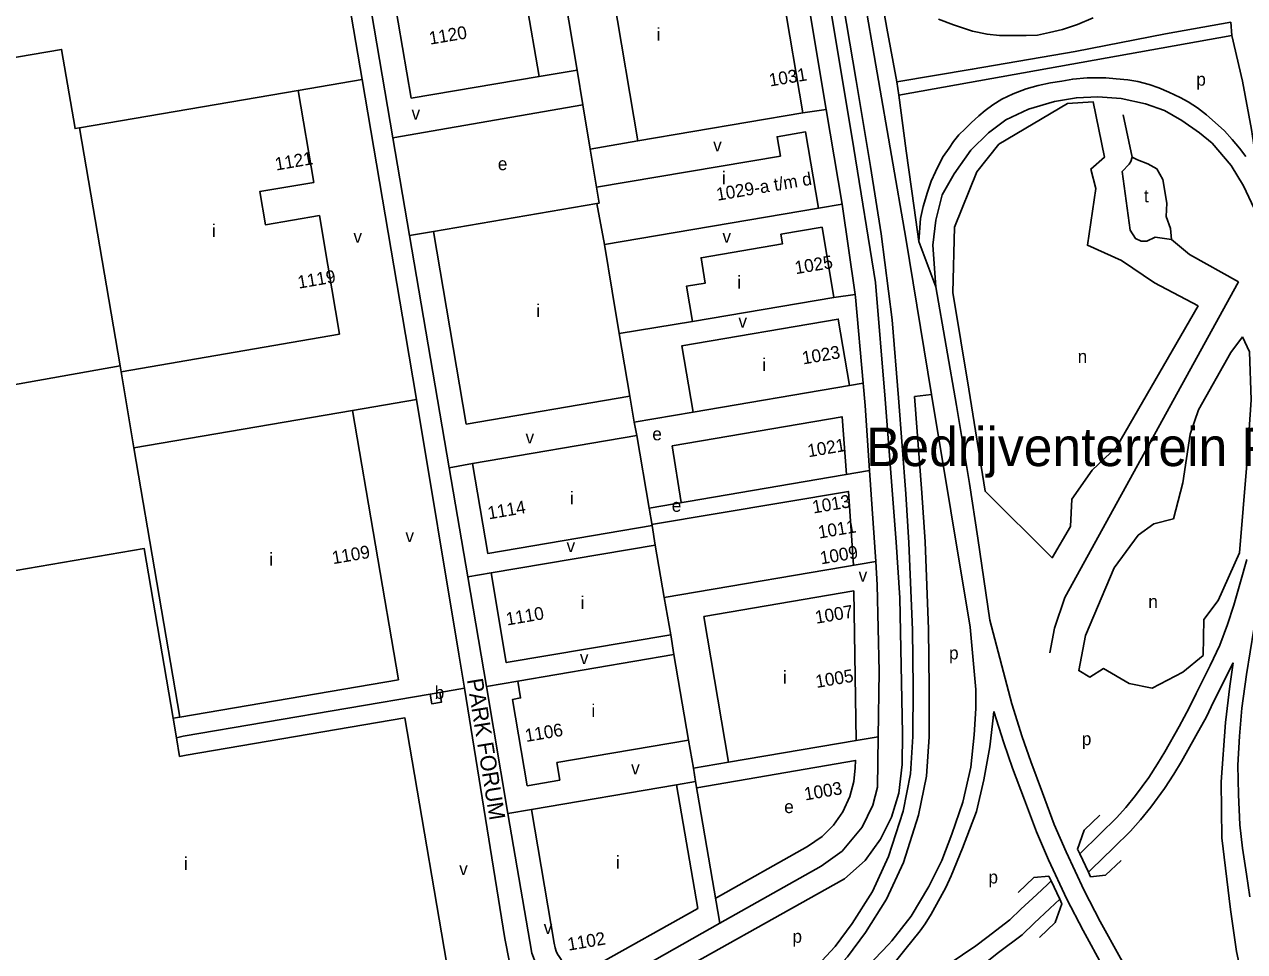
# Model space of a CAD drawing. Extents: x 154320 to 156262, y 382651 to 384180.
# Drawn here: x 154804.6 to 155184.2, y 383220 to 383508.4 of the extents above; entities that cross this region are included whole.
import ezdxf

# ---------------------------------------------------------------- set-up
doc = ezdxf.new("R2010")
doc.units = 0
for name, color, linetype in [('BLT_Basislijn', 7, 'Continuous'), ('BLT_Bebouwing', 7, 'Continuous'), ('BLT_Centroide', 7, 'Continuous'), ('BLT_Huisnummer', 7, 'Continuous'), ('BLT_Huisnummer_reeks', 7, 'Continuous'), ('BLT_Huisnummer_zonder_bebouwing', 7, 'Continuous'), ('BLT_Onderverdeling_panden', 7, 'Continuous'), ('BLT_Plantopo', 7, 'Continuous'), ('BLT_Sport_parknaam', 7, 'Continuous'), ('BLT_Straatnaam', 7, 'Continuous'), ('BLT_Vlakafsluiter', 7, 'Continuous')]:
    doc.layers.add(name, color=color, linetype=linetype)

msp = doc.modelspace()

# ---------------------------------------------------------------- linework, layer by layer
at = {"layer": 'BLT_Basislijn'}
for p, q in [((154904.98, 383556.75), (154919.23, 383473.09)), ((154976.53, 383494.14), (154969.79, 383534.71)), ((155179.9, 383509.09), (155180.25, 383504.95)), ((154889.72, 383487.81), (154909.63, 383491.26)), ((154964.69, 383492.17), (154976.53, 383494.14)), ((154978.32, 383483.35), (154976.53, 383494.14)), ((155075.98, 383490.54), (155076.69, 383486.41)), ((154919.23, 383473.09), (154978.32, 383483.35)), ((154980.61, 383469.6), (154978.32, 383483.35)), ((155149.29, 383467.05), (155146.42, 383480.21)), ((154919.23, 383473.09), (154924.4, 383442.77)), ((155051.66, 383451.27), (155058.97, 383452.51)), ((154931.81, 383444.01), (154924.4, 383442.77)), ((154924.4, 383442.77), (154936.71, 383370.48)), ((155086.84, 383393.25), (155078.78, 383441.91)), ((155056.45, 383423.4), (155063.02, 383424.42)), ((155012.45, 383416.01), (154989.66, 383412.19)), ((154834.64, 383400.33), (154838.62, 383376.66)), ((155061.31, 383396.08), (155065.58, 383396.8)), ((154994.33, 383384.69), (154992.97, 383392.72)), ((155081.53, 383392.66), (155086.84, 383393.25)), ((155098.84, 383320.87), (155086.84, 383393.25)), ((154906.67, 383388.27), (154926.55, 383391.66)), ((155012.64, 383387.8), (154994.33, 383384.69)), ((154994.33, 383384.69), (154995.07, 383380.54)), ((154943.97, 383371.79), (154936.71, 383370.48)), ((154936.71, 383370.48), (154942.49, 383336.54)), ((155067.56, 383369.59), (154998.94, 383357.92)), ((155069.45, 383341.32), (155067.56, 383369.59)), ((155000.87, 383346.44), (154999.86, 383352.54)), ((155100.63, 383301.5), (155098.84, 383320.87)), ((154933.81, 383300.57), (154941.46, 383301.92)), ((154958.07, 383304.07), (154948.31, 383302.4)), ((154853.92, 383287), (154930.79, 383300.07)), ((154850.83, 383292.59), (154852.87, 383292.89)), ((154851.86, 383286.5), (154853.92, 383287)), ((155011.21, 383285.75), (155012.71, 383277.03)), ((155063.33, 383285.63), (155070.22, 383286.8)), ((155023.64, 383278.89), (155012.71, 383277.03)), ((155012.71, 383277.03), (155013.42, 383272.88)), ((155013.42, 383272.88), (155007.49, 383271.87)), ((155013.42, 383272.88), (155020.99, 383228.79)), ((154962.3, 383264.15), (154955.03, 383262.9))]:
    msp.add_line(p, q, dxfattribs=at)
for points in [[(155023.31, 383706.47), (155038.2, 383616.87), (155062.68, 383469.79), (155069.36, 383428.11)], [(155036.13, 383685.14), (155036.76, 383683.03), (155038.71, 383673.47), (155078.78, 383441.91)], [(155048.57, 383212.61), (155056.82, 383221.58), (155062.17, 383228.69), (155068.4, 383238.67), (155073.45, 383249.51), (155077.96, 383263.67), (155080.28, 383275.23), (155081.04, 383286.89), (155081.1, 383302.07), (155080.89, 383320.08), (155079.8, 383347.13), (155078.77, 383362.31), (155076.55, 383392.27), (155074.59, 383416.48), (155071.13, 383443.2), (155067.82, 383464.17), (155063.32, 383490.92), (155056.28, 383532.64), (155051.11, 383563.15)], [(155054.06, 383481.93), (155045.91, 383530.45), (155043.13, 383547.03)], [(155075.98, 383490.54), (155072.91, 383507.2), (155071.26, 383516.65), (155069.72, 383523.86), (155068.19, 383529.88)], [(154909.63, 383491.26), (154903.62, 383526.48)], [(155088.97, 383510.03), (155093.69, 383508.26), (155099.6, 383506.25), (155104.08, 383505.31), (155107.98, 383504.95), (155112.47, 383504.95), (155116.25, 383504.95), (155119.79, 383505.07), (155123.57, 383505.9), (155127.58, 383506.84), (155132.19, 383508.38), (155137.15, 383510.39)], [(155179.9, 383509.09), (155159.58, 383505.43), (155131.48, 383499.99), (155099.48, 383494.44), (155075.98, 383490.54)], [(155076.69, 383486.41), (155180.25, 383504.95)], [(155180.25, 383504.95), (155183.56, 383490.78), (155186.39, 383475.66), (155187.57, 383467.39), (155187.93, 383460.65)], [(154926.55, 383391.66), (154923.17, 383411.93), (154909.63, 383491.26)], [(155184.62, 383467.27), (155182.61, 383469.87), (155180.37, 383472.59), (155178.01, 383475.3), (155175.05, 383477.9), (155172.34, 383480.26), (155169.62, 383482.39), (155166.67, 383484.28), (155164.19, 383485.7), (155160.65, 383487.35), (155157.58, 383488.65), (155154.51, 383489.71), (155150.97, 383490.66), (155147.89, 383491.13), (155144.23, 383491.49), (155141.05, 383491.72), (155138.09, 383491.72), (155135.26, 383491.72), (155130.77, 383491.37), (155127.35, 383490.78), (155123.81, 383490.19), (155120.03, 383489.36), (155116.25, 383488.3), (155112.23, 383486.76), (155108.69, 383485.11)], [(155082.83, 383440.81), (155081.41, 383451.32), (155078.93, 383469.04), (155076.69, 383486.41)], [(155108.69, 383485.11), (155105.86, 383483.34), (155103.49, 383481.56), (155101.49, 383479.91), (155099.13, 383477.78), (155097.24, 383475.89), (155095.35, 383474), (155093.69, 383471.99), (155092.28, 383469.87), (155090.39, 383467.27), (155089.44, 383465.38), (155088.03, 383462.54), (155086.73, 383459.59), (155085.55, 383456.16), (155084.25, 383451.79), (155083.42, 383448.01), (155082.83, 383440.81)], [(155088.2, 383426.75), (155087.26, 383439.74), (155088.2, 383447.54), (155090.09, 383455.34), (155093.87, 383461.95), (155099.07, 383469.28), (155104.5, 383474.71), (155109.93, 383478.73), (155117.02, 383482.03), (155125.05, 383484.4), (155131.89, 383485.58), (155138.51, 383485.81)], [(155138.51, 383485.81), (155145.83, 383485.34), (155153.39, 383483.69), (155159.29, 383481.56), (155164.72, 383478.49), (155170.15, 383474.71), (155174.17, 383471.4), (155180.07, 383464.55), (155183.85, 383458.17), (155187.16, 383451.08), (155188.81, 383444.47)], [(155054.06, 383481.93), (155046.76, 383480.84)], [(155058.97, 383452.51), (155054.06, 383481.93)], [(154995.44, 383472.21), (154980.61, 383469.6)], [(154980.61, 383469.6), (154982.6, 383457.71)], [(155161.5, 383441.46), (155156.39, 383442.16), (155153.76, 383440.93), (155152.02, 383440.93), (155150.24, 383441.74), (155148.67, 383444.37), (155146.08, 383462.61), (155148.26, 383464.88), (155148.81, 383465.75), (155149.29, 383467.05)], [(155149.29, 383467.05), (155150.92, 383466.23), (155154.14, 383464.99), (155156.9, 383463.46), (155158.81, 383460.19), (155159.98, 383452.82), (155159.86, 383448.62), (155161.21, 383444.92), (155161.5, 383441.46)], [(155063.02, 383424.42), (155058.97, 383452.51)], [(155161.5, 383441.46), (155167.08, 383436.78), (155182.28, 383428.33)], [(155193.98, 383439.68), (155194.8, 383434.25), (155195.75, 383423.85), (155196.46, 383412.51), (155196.93, 383398.69), (155196.81, 383385.34), (155196.69, 383371.28), (155195.75, 383362.66), (155194.09, 383353.44), (155191.97, 383342.81), (155187.13, 383320.25), (155184.77, 383306.19), (155183.35, 383295.68), (155182.64, 383286.93), (155182.17, 383277.95), (155182.29, 383268.86), (155182.76, 383259.41), (155183.59, 383252.08), (155184.77, 383244.05), (155185.83, 383236.96)], [(154996.32, 383207.14), (155059.77, 383242.54), (155066.19, 383248.26), (155070.95, 383254.88), (155074.34, 383261.77), (155076.64, 383269.21), (155077.68, 383278.13), (155077.79, 383287.81), (155076.91, 383330.03), (155075.76, 383347.31), (155072.43, 383391.78), (155069.36, 383428.11)], [(155101.19, 383348.54), (155098.59, 383365.55), (155094.58, 383389.89), (155088.2, 383426.75)], [(155182.28, 383428.33), (155128.33, 383330.11), (155125.03, 383320.55), (155123.64, 383312.91)], [(154989.66, 383412.19), (154987.4, 383425.43)], [(155065.58, 383396.8), (155063.14, 383423.56), (155063.02, 383424.42)], [(155067.56, 383369.59), (155066.21, 383389.86), (155065.58, 383396.8)], [(155054.29, 383211.44), (155060.67, 383218.37), (155066.3, 383225.86), (155072.8, 383236.28), (155078.11, 383247.69), (155082.81, 383262.42), (155085.25, 383274.57), (155086.04, 383286.72), (155086.1, 383302.09), (155085.89, 383320.21), (155084.8, 383347.4), (155083.76, 383362.67), (155081.53, 383392.66)], [(154941.46, 383301.92), (154939.76, 383312.44), (154926.55, 383391.66)], [(155104.98, 383323.07), (155101.19, 383348.54)], [(155003.67, 383330.13), (155069.45, 383341.32)], [(155070.22, 383286.8), (155070.53, 383307.05), (155069.93, 383334.07), (155069.45, 383341.32)], [(155132.91, 383250.38), (155139.25, 383256.56), (155144.36, 383261.52), (155147.25, 383264.79), (155150.32, 383268.55), (155154.4, 383274.12), (155157.15, 383278.41), (155159.45, 383282.09), (155163.82, 383290.01), (155167.01, 383295.76), (155169.14, 383300.27), (155173.52, 383308.98), (155176.51, 383315.32), (155178.87, 383321.66), (155180.87, 383327.77), (155182.98, 383334.97), (155184.9, 383341.94)], [(154949.76, 383337.78), (154942.49, 383336.54)], [(154942.49, 383336.54), (154948.31, 383302.4)], [(155104.98, 383323.07), (155111.77, 383297), (155115.05, 383286.74), (155117.68, 383279.04), (155121.32, 383269.31), (155125, 383259.47), (155128.71, 383250.96), (155134.33, 383238.91), (155139.25, 383229.29), (155145.56, 383217.96), (155151.05, 383208.9), (155157.44, 383199.46), (155163.16, 383190.49), (155170.12, 383180.15), (155177.37, 383170.22), (155184.2, 383161.54)], [(155006.66, 383312.34), (155005.67, 383318.49)], [(155135.62, 383244.68), (155136.5, 383245.5), (155143.44, 383252.26), (155148.7, 383257.37), (155151.82, 383260.91), (155155.07, 383264.87), (155159.35, 383270.72), (155162.22, 383275.2), (155164.63, 383279.04), (155169.07, 383287.1), (155172.35, 383293.02), (155174.53, 383297.64), (155180.64, 383309.78)], [(155180.64, 383309.78), (155179.65, 383302.54), (155178.31, 383291.22), (155176.97, 383272.74), (155177.19, 383255.3), (155179.8, 383233.1)], [(154967.74, 383198.42), (154968.4, 383199.95), (154968.1, 383201.56), (154966.98, 383202.8), (154964.01, 383204.72), (154960.79, 383207.32), (154958.01, 383211.21), (154955.47, 383216.66), (154954.05, 383224.08), (154941.46, 383301.92)], [(154948.31, 383302.4), (154955.03, 383262.9)], [(155100.63, 383301.5), (155100.55, 383295.54), (155100.1, 383287.34), (155099.06, 383277.36), (155096.53, 383266.48), (155093.1, 383256.5), (155089.98, 383248.3), (155085.95, 383240.25), (155080.44, 383231.01), (155074.48, 383223.26), (155073.56, 383222.3)], [(155106.23, 383294.63), (155105.76, 383290.76), (155104.94, 383283.65), (155103.05, 383273.41), (155100.81, 383263.57), (155096.49, 383252.1), (155092.88, 383243.53), (155091.29, 383239.85), (155089.51, 383236.63), (155086.75, 383231.55), (155084.8, 383228.64)], [(155106.23, 383294.63), (155109.35, 383284.86), (155112.03, 383277.02), (155115.7, 383267.21), (155119.44, 383257.22), (155123.24, 383248.49), (155128.94, 383236.28), (155133.95, 383226.47), (155140.37, 383214.95), (155146, 383205.66), (155152.43, 383196.17), (155160.82, 383182.98)], [(155020.99, 383228.79), (155052.43, 383246.53), (155058.97, 383251.2), (155065.21, 383258.69), (155068.52, 383265.55), (155069.98, 383271.15), (155070.22, 383286.8)], [(154955.03, 383262.9), (154962.43, 383219.49), (154963.8, 383215.97), (154965.69, 383213.14), (154967.91, 383210.89), (154970.82, 383209), (154975.1, 383207.49), (154980.13, 383207.29), (154984.71, 383208.39)], [(155139.19, 383262.36), (155134.3, 383257.72), (155132.21, 383251.86), (155132.91, 383250.38)], [(155132.91, 383250.38), (155135.62, 383244.68)], [(155135.62, 383244.68), (155136.31, 383243.24), (155140.94, 383243.71), (155145.82, 383248.32)], [(155093.83, 383217.17), (155096.48, 383218.97), (155100.63, 383221.74), (155104.04, 383224.39), (155111.14, 383229.79), (155114.63, 383233.11), (155119.55, 383237.73), (155122.86, 383240.84), (155124.01, 383241.96)], [(155113.74, 383238.36), (155118.65, 383242.96), (155123.29, 383243.47), (155124.01, 383241.96)], [(155124.01, 383241.96), (155126.71, 383236.23)], [(155097.57, 383212.45), (155099.83, 383213.99), (155104.15, 383216.88), (155107.7, 383219.64), (155115.03, 383225.21), (155118.75, 383228.75), (155123.66, 383233.36), (155126.71, 383236.23)], [(155126.71, 383236.23), (155127.37, 383234.82), (155125.27, 383228.96), (155120.38, 383224.34)], [(155179.8, 383233.1), (155181.73, 383219.99), (155184.12, 383208.96), (155186.05, 383200.91), (155187.54, 383194.95), (155190.37, 383187.8), (155192.61, 383182.58), (155195.58, 383176.47), (155199.01, 383170.07), (155202.73, 383163.66), (155206.61, 383158.74), (155211.97, 383152.18), (155217.63, 383146.37), (155223.74, 383141.16), (155229.25, 383137.28), (155236.55, 383132.66), (155242.95, 383129.23), (155248.17, 383127.3), (155255.17, 383125.06), (155263.36, 383121.93), (155269.62, 383120)], [(154984.71, 383208.39), (154986.5, 383209.34), (155020.99, 383228.79)], [(155056.26, 383199.61), (155061.88, 383203.54), (155067.21, 383207.87), (155070.61, 383211.19), (155074.34, 383215.27), (155078.54, 383220.51), (155083.29, 383226.42), (155084.8, 383228.64)], [(155073.56, 383222.3), (155066.89, 383215.37), (155061.67, 383210.6), (155050.87, 383201.66)]]:
    msp.add_lwpolyline(points, dxfattribs=at)
for points in [[(155169.73, 383420.84), (155144.41, 383376.88), (155136.83, 383369.75), (155130.45, 383360.75), (155130.04, 383352.22), (155124.39, 383342.47), (155103.49, 383363.14), (155098.47, 383394.88), (155093.4, 383424.98), (155093.91, 383445.3), (155100.94, 383462.49), (155107.74, 383471.09), (155129.14, 383483.74), (155137.14, 383484.28), (155140.63, 383467.07), (155136.38, 383463.41), (155137.91, 383457.31), (155135.32, 383439.71), (155145.95, 383434.99), (155156.14, 383427.97)], [(155183.57, 383411.21), (155185.73, 383406.58), (155186.25, 383391.6), (155184.96, 383371.6), (155182.67, 383343.96), (155176.02, 383329.21), (155171.58, 383323.23), (155171.38, 383312.11), (155165.03, 383306.92), (155155.47, 383301.87), (155148.33, 383303.32), (155140.34, 383308.02), (155136.11, 383305.37), (155132.63, 383307.36), (155134.7, 383318.27), (155143.66, 383339.38), (155151.14, 383349.48), (155155.97, 383353.05), (155162.08, 383354.62), (155165.05, 383365.81), (155167.31, 383380.95), (155169.91, 383388.52), (155179.96, 383406.31)]]:
    msp.add_lwpolyline(points, close=True, dxfattribs=at)
at = {"layer": 'BLT_Bebouwing'}
for p, q in [((154912.56, 383558.14), (154924.85, 383485.44)), ((155036.82, 383540.02), (155046.76, 383480.84)), ((154995.44, 383472.21), (154985.47, 383531.41)), ((154924.85, 383485.44), (154964.69, 383492.17)), ((154821.72, 383476.24), (154889.72, 383487.81)), ((155046.76, 383480.84), (154995.44, 383472.21)), ((154983.44, 383452.77), (154982.6, 383457.71)), ((154982.69, 383452.67), (154983.44, 383452.77)), ((154982.69, 383452.67), (154931.81, 383444.01)), ((155051.66, 383451.27), (154985.03, 383439.9)), ((154931.81, 383444.01), (154941.98, 383383.99)), ((154985.03, 383439.9), (154987.4, 383425.43)), ((155056.45, 383423.4), (155012.45, 383416.01)), ((154992.97, 383392.72), (154989.66, 383412.19)), ((154834.64, 383400.33), (154834.33, 383402.15)), ((154941.98, 383383.99), (154992.97, 383392.72)), ((154943.97, 383371.79), (154995.07, 383380.54)), ((154995.07, 383380.54), (154998.94, 383357.92)), ((154838.62, 383376.66), (154852.87, 383292.89)), ((154998.94, 383357.92), (154999.86, 383352.54)), ((155003.67, 383330.13), (155000.87, 383346.44)), ((155015.93, 383324.2), (155062.64, 383332.15)), ((155062.64, 383332.15), (155063.33, 383285.63)), ((155023.64, 383278.89), (155015.93, 383324.2)), ((154958.07, 383304.07), (155006.66, 383312.34)), ((155006.66, 383312.34), (155011.21, 383285.75)), ((154850.83, 383292.59), (154851.86, 383286.5)), ((155011.21, 383285.75), (154970.24, 383278.79)), ((155063.33, 383285.63), (155023.64, 383278.89)), ((154970.24, 383278.79), (154971.18, 383273.27)), ((154971.18, 383273.27), (154961.04, 383271.55))]:
    msp.add_line(p, q, dxfattribs=at)
for points in [[(154964.69, 383492.17), (154960.72, 383515.62), (154950.86, 383513.94), (154942.46, 383563.23)], [(154747.25, 383488.9), (154816.1, 383500.63), (154820.31, 383476), (154821.72, 383476.24)], [(154747.25, 383488.9), (154754.6, 383445.61), (154764.83, 383447.08), (154774.29, 383391.51), (154834.33, 383402.15)], [(154889.72, 383487.81), (154894.6, 383459.23), (154877.77, 383456.37), (154879.54, 383446.05), (154896.36, 383448.91), (154898.99, 383433.47), (154902.62, 383412.07)], [(154982.6, 383457.71), (155039.78, 383467.44), (155038.76, 383473.42), (155047.63, 383474.93), (155051.66, 383451.27)], [(155039.88, 383443.16), (155052.78, 383445.3), (155056.45, 383423.4)], [(155012.45, 383416.01), (155010.6, 383426.97), (155016.41, 383427.94), (155015.09, 383435.8), (155040.4, 383440.11), (155039.88, 383443.16)], [(155061.31, 383396.08), (155057.8, 383416.71), (155009.13, 383408.44), (155012.64, 383387.8)], [(154902.62, 383412.07), (154834.64, 383400.33)], [(155012.64, 383387.8), (155061.31, 383396.08)], [(154906.67, 383388.27), (154838.62, 383376.66)], [(154852.87, 383292.89), (154920.91, 383304.51), (154906.67, 383388.27)], [(154999.86, 383352.54), (154948.73, 383343.84), (154943.97, 383371.79)], [(155000.87, 383346.44), (154949.76, 383337.78)], [(154761.86, 383331.67), (154841.85, 383345.32), (154850.83, 383292.59)], [(154949.76, 383337.78), (154954.48, 383309.84), (155005.67, 383318.49)], [(155005.67, 383318.49), (155003.67, 383330.13)], [(154961.04, 383271.55), (154956.45, 383298.43), (154958.96, 383298.86), (154958.07, 383304.07)], [(154930.78, 383300.07), (154931.29, 383297.04), (154934.34, 383297.58), (154933.81, 383300.57)], [(154933.81, 383300.57), (154930.78, 383300.07)], [(154854.94, 383281.04), (154922.94, 383292.64), (154938.17, 383203.28), (154923.05, 383200.72), (154925.91, 383183.81), (154890.47, 383163.81), (154886.23, 383188.76), (154871.01, 383186.17), (154876.19, 383155.75)], [(154851.86, 383286.5), (154852.85, 383280.68), (154854.94, 383281.04)], [(155007.49, 383271.87), (155014.06, 383233.41), (154981.87, 383215.27), (154980.98, 383214.94), (154979.36, 383214.56), (154977.5, 383214.51), (154975.65, 383214.87), (154973.96, 383215.59), (154972.51, 383216.59), (154971.62, 383217.47), (154970.91, 383218.4), (154970.44, 383219.19), (154970.01, 383220.12), (154969.68, 383221.16), (154969.4, 383222.53), (154962.3, 383264.15)], [(154962.3, 383264.15), (155007.49, 383271.87)]]:
    msp.add_lwpolyline(points, dxfattribs=at)
at = {"layer": 'BLT_Onderverdeling_panden'}
for p, q in [((154834.33, 383402.15), (154821.72, 383476.24)), ((154982.69, 383452.67), (154985.03, 383439.9))]:
    msp.add_line(p, q, dxfattribs=at)
at = {"layer": 'BLT_Plantopo'}
for points in [[(155008.95, 383359.66), (155006.14, 383377.26), (155058.97, 383386.32), (155060.36, 383368.39)], [(154999.7, 383352.83), (155060.93, 383363.1), (155062.55, 383340.14)], [(155013.74, 383270.91), (155063.17, 383279.45), (155063.05, 383277.12), (155062.68, 383272.86), (155061.42, 383268.16), (155059.23, 383263.39), (155056.3, 383259.24), (155052.74, 383255.8), (155048.21, 383252.63), (155019.54, 383236.5)]]:
    msp.add_lwpolyline(points, dxfattribs=at)
at = {"layer": 'BLT_Vlakafsluiter'}
msp.add_line((155082.83, 383440.81), (155088.2, 383426.75), dxfattribs=at)

# ---------------------------------------------------------------- texts
at = {"layer": 'BLT_Centroide'}
for s, p in [('i', (155001.26, 383503.29)), ('p', (155169.2, 383489.33)), ('e', (154951.87, 383463.05)), ('i', (155021.61, 383458.69)), ('t', (155152.9, 383453.05)), ('i', (154862.91, 383442.23)), ('i', (155026.34, 383426.19)), ('i', (154963.85, 383417.33)), ('i', (155034.17, 383400.55)), ('n', (155132.28, 383403.1)), ('e', (154999.93, 383379.01)), ('i', (154974.29, 383359.07)), ('e', (155005.98, 383356.77)), ('i', (154880.76, 383340.05)), ('i', (154977.64, 383326.51)), ('n', (155154.26, 383326.84)), ('p', (155092.26, 383310.86)), ('i', (155040.58, 383303.33)), ('b', (154932.22, 383298.56)), ('i', (154980.98, 383292.91)), ('p', (155133.58, 383284.17)), ('e', (155040.97, 383263.04)), ('i', (154854.18, 383245.39)), ('i', (154988.61, 383245.74)), ('p', (155104.53, 383241.15)), ('p', (155043.54, 383222.7))]:
    msp.add_text(s, height=4, dxfattribs=at).set_placement(p)
for p in [(154924.99, 383478.79), (155018.85, 383468.89), (154906.91, 383440.47), (155021.73, 383440.47), (155026.71, 383414.09), (154960.47, 383378.04), (154923.09, 383347.35), (154973.22, 383344.23), (155064.11, 383335.05), (154977.39, 383309.42), (154993.32, 383275.12), (154939.82, 383243.77), (154966.12, 383225.46)]:
    msp.add_text('v', height=4, rotation=359.5, dxfattribs=at).set_placement(p)
at = {"layer": 'BLT_Huisnummer'}
for s, rotation, p in [('1025', 9.6197, (155044.6, 383430.67)), ('1023', 9.6197, (155046.89, 383402.6)), ('1114', 9.7394, (154949.05, 383354.39)), ('1109', 9.7394, (154900.6, 383340.46)), ('1110', 9.7394, (154954.73, 383321.38)), ('1106', 9.5808, (154960.65, 383285.14))]:
    msp.add_text(s, height=4, rotation=rotation, dxfattribs=at).set_placement(p)
at = {"layer": 'BLT_Huisnummer_reeks'}
for s, rotation, p in [('1120', 9.6197, (154930.78, 383502.07)), ('1031', 9.5294, (155036.56, 383489.05)), ('1121', 9.7394, (154882.87, 383462.91)), ('1029-a t/m d', 9.6624, (155020.19, 383453.51)), ('1119', 9.7394, (154889.92, 383426.16))]:
    msp.add_text(s, height=4, rotation=rotation, dxfattribs=at).set_placement(p)
at = {"layer": 'BLT_Huisnummer_zonder_bebouwing'}
for s, rotation, p in [('1021', 9.6197, (155048.55, 383373.72)), ('1013', 9.6197, (155050.07, 383356.22)), ('1011', 9.6197, (155051.85, 383348.41)), ('1009', 9.6197, (155052.46, 383340.4)), ('1007', 9.6623, (155050.94, 383321.92)), ('1005', 9.6623, (155051.06, 383301.95)), ('1003', 9.6623, (155047.52, 383266.95)), ('1102', 9.6614, (154973.87, 383220.22))]:
    msp.add_text(s, height=4, rotation=rotation, dxfattribs=at).set_placement(p)
at = {"layer": 'BLT_Sport_parknaam'}
msp.add_text('Bedrijventerrein Park Forum', height=12, dxfattribs=at).set_placement((155066.45, 383370.98))
at = {"layer": 'BLT_Straatnaam'}
msp.add_text('PARK FORUM', height=5, rotation=279.1888, dxfattribs=at).set_placement((154942.22, 383304.57))

doc.saveas('drawing.dxf')
